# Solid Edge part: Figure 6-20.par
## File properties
Author: CADCIM
Template: iso part.par
Last saved by: TIET
Revision: 3
Application: Solid Edge
Accuracy: 0.990
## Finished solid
Body 1: solid body, 44 faces, 84 edges, 42 vertices.
  Faces by surface: cylinder 21, plane 11, sphere 11, torus 1
  Edges by curve: line 44, circle 37, ellipse 3
Bounding box of the edges (mm; curved faces can reach further): 37.751 x 27.006 x 17.217, from (-18.8757, -27.0057, 3.164) to (18.8757, 0, 20.3814).
Cylindrical faces by radius (mm): R1 x20, R4.7256 x1
Toroidal faces (ring radius, tube radius in mm): R3.7256 r1 x1
Spherical faces by radius (mm): R1 x11
Planar faces by outward normal: +x 2, +y 1, +z 4, -x 1, -y 2, -z 1
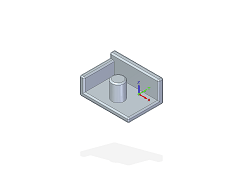
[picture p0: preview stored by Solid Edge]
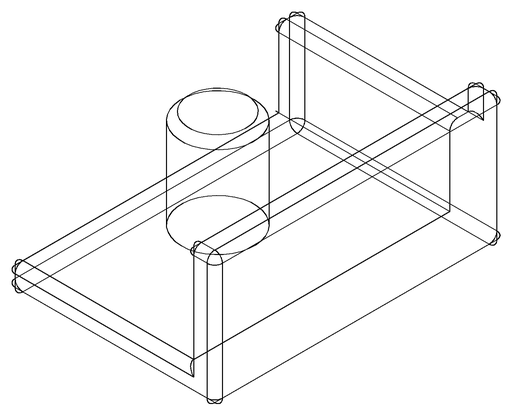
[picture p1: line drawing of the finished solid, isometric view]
